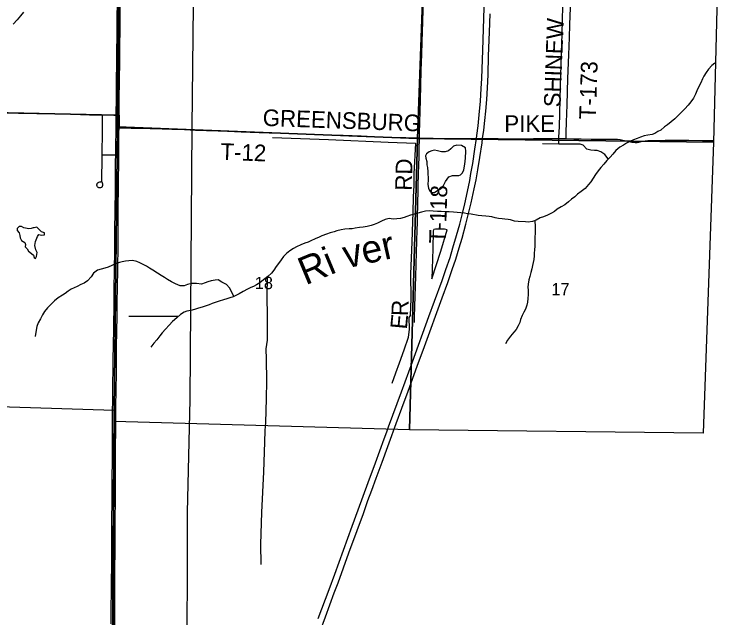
# Model space of a CAD drawing. Extents: x -107 to 120, y -81 to 213.
# Drawn here: x -76.39 to -63.66, y -41 to -30.12 of the extents above; entities that cross this region are included whole.
import ezdxf

# ---------------------------------------------------------------- set-up
doc = ezdxf.new("R2010")
doc.units = 0
for name, color, linetype in [('GM_X_Interstate_Route', 7, 'Continuous'), ('GM_X_Major_River', 7, 'Continuous'), ('GM_X_Minor_Lake', 7, 'Continuous'), ('GM_X_Minor_River', 7, 'Continuous'), ('GM_X_Minor_River_Text', 7, 'Continuous'), ('GM_X_Rail_Line', 7, 'Continuous'), ('GM_X_Section', 7, 'Continuous'), ('GM_X_Section_Text', 7, 'Continuous'), ('GM_X_State_Route', 7, 'Continuous'), ('GM_X_Township', 7, 'Continuous'), ('GM_X_Township_Road', 7, 'Continuous'), ('GM_X_Township_Road_Text', 7, 'Continuous')]:
    doc.layers.add(name, color=color, linetype=linetype)

msp = doc.modelspace()

# ---------------------------------------------------------------- linework, layer by layer
at = {"layer": 'GM_X_Interstate_Route'}
for points in [[(-70.911, -41.015), (-70.716, -40.491), (-70.616, -40.214), (-70.459, -39.782), (-70.302, -39.35), (-70.194, -39.057), (-70.014, -38.564), (-69.883, -38.21), (-69.726, -37.778), (-69.697, -37.701), (-69.67, -37.63), (-69.645, -37.563), (-69.414, -36.931), (-69.217, -36.391), (-68.919, -35.574), (-68.817, -35.297), (-68.682, -34.926), (-68.612, -34.725), (-68.539, -34.507), (-68.486, -34.334), (-68.421, -34.114), (-68.364, -33.908), (-68.315, -33.717), (-68.273, -33.541), (-68.224, -33.317), (-68.184, -33.124), (-68.161, -32.995), (-68.13, -32.817), (-68.09, -32.557), (-68.062, -32.365), (-68.055, -32.313), (-68.033, -32.134), (-68.012, -31.938), (-67.991, -31.693), (-67.976, -31.463), (-67.967, -31.283), (-67.95, -30.774), (-67.93, -30.2), (-67.911, -29.61)], [(-70.883, -41.264), (-70.782, -40.985), (-70.623, -40.554), (-70.556, -40.369), (-70.359, -39.829), (-70.213, -39.428), (-70.1, -39.12), (-70.017, -38.888), (-69.949, -38.703), (-69.868, -38.488), (-69.762, -38.196), (-69.66, -37.918), (-69.587, -37.717), (-69.557, -37.633), (-69.509, -37.501), (-69.407, -37.224), (-69.293, -36.916), (-69.131, -36.468), (-69.001, -36.114), (-68.68, -35.235), (-68.579, -34.958), (-68.498, -34.725), (-68.436, -34.539), (-68.372, -34.335), (-68.322, -34.162), (-68.252, -33.909), (-68.204, -33.718), (-68.158, -33.526), (-68.102, -33.27), (-68.07, -33.109), (-68.038, -32.931), (-68.001, -32.705), (-67.962, -32.445), (-67.952, -32.365), (-67.932, -32.217), (-67.911, -32.038), (-67.895, -31.875), (-67.878, -31.662), (-67.864, -31.449), (-67.854, -31.22), (-67.843, -30.876), (-67.828, -30.449), (-67.817, -30.121)]]:
    msp.add_lwpolyline(points, dxfattribs=at)
at = {"layer": 'GM_X_Major_River'}
for points in [[(-76.22, -30.089), (-76.275, -30.153), (-76.335, -30.225), (-76.405, -30.307)], [(-63.769, -31.007), (-63.824, -31.05), (-63.882, -31.114), (-63.927, -31.175), (-63.97, -31.24), (-63.993, -31.292), (-64.021, -31.362), (-64.066, -31.441), (-64.095, -31.503), (-64.115, -31.567), (-64.154, -31.638), (-64.199, -31.703), (-64.251, -31.765), (-64.31, -31.832), (-64.374, -31.899), (-64.441, -31.962), (-64.492, -32.009), (-64.557, -32.062), (-64.622, -32.119), (-64.673, -32.154), (-64.742, -32.213), (-64.793, -32.238), (-64.85, -32.273), (-64.9, -32.292), (-64.977, -32.307), (-65.041, -32.318), (-65.108, -32.341), (-65.169, -32.366), (-65.235, -32.389), (-65.302, -32.42), (-65.359, -32.451), (-65.412, -32.482), (-65.479, -32.523), (-65.554, -32.579), (-65.605, -32.645), (-65.654, -32.7), (-65.714, -32.759), (-65.767, -32.826), (-65.822, -32.887), (-65.871, -32.947), (-65.917, -33.012), (-65.962, -33.079), (-66.005, -33.143), (-66.043, -33.194), (-66.104, -33.263), (-66.179, -33.322), (-66.24, -33.365), (-66.293, -33.418), (-66.348, -33.459), (-66.405, -33.505), (-66.471, -33.562), (-66.537, -33.596), (-66.606, -33.639), (-66.659, -33.678), (-66.71, -33.71), (-66.785, -33.748), (-66.856, -33.775), (-66.918, -33.792), (-66.989, -33.839), (-67.054, -33.858), (-67.13, -33.871), (-67.18, -33.864), (-67.311, -33.861), (-67.379, -33.852), (-67.447, -33.833)], [(-67.55, -33.817), (-67.602, -33.812), (-67.668, -33.804), (-67.728, -33.792), (-67.786, -33.778), (-67.836, -33.77), (-67.894, -33.765), (-67.968, -33.761), (-68.031, -33.751), (-68.159, -33.731), (-68.221, -33.72), (-68.277, -33.712), (-68.343, -33.702), (-68.409, -33.7), (-68.479, -33.695), (-68.555, -33.687), (-68.615, -33.687), (-68.697, -33.683), (-68.766, -33.679), (-68.842, -33.672), (-68.904, -33.67), (-68.978, -33.674), (-69.05, -33.692), (-69.118, -33.708), (-69.186, -33.73), (-69.253, -33.749), (-69.317, -33.769), (-69.367, -33.787), (-69.431, -33.805), (-69.499, -33.815), (-69.565, -33.817), (-69.637, -33.808), (-69.706, -33.824), (-69.772, -33.854), (-69.842, -33.888), (-69.908, -33.914), (-69.958, -33.93), (-70.032, -33.952), (-70.101, -33.965), (-70.169, -33.971), (-70.245, -33.979), (-70.303, -33.993), (-70.355, -33.995), (-70.431, -34.001), (-70.497, -34.01), (-70.578, -34.026), (-70.628, -34.044), (-70.698, -34.066), (-70.766, -34.088), (-70.846, -34.116), (-70.897, -34.14), (-70.967, -34.171), (-71.045, -34.207), (-71.095, -34.233), (-71.155, -34.253), (-71.226, -34.279), (-71.304, -34.319), (-71.356, -34.349), (-71.422, -34.389), (-71.482, -34.435), (-71.541, -34.491), (-71.583, -34.553), (-71.631, -34.617), (-71.672, -34.673), (-71.712, -34.739), (-71.754, -34.793), (-71.82, -34.851), (-71.899, -34.913), (-71.967, -34.965), (-72.023, -35.001), (-72.077, -35.029), (-72.129, -35.052), (-72.186, -35.078), (-72.264, -35.122), (-72.336, -35.164), (-72.386, -35.188), (-72.445, -35.216), (-72.505, -35.238), (-72.561, -35.254), (-72.621, -35.272), (-72.695, -35.294), (-72.767, -35.321), (-72.82, -35.341), (-72.878, -35.363), (-72.948, -35.387), (-73.002, -35.405), (-73.072, -35.425), (-73.142, -35.447), (-73.207, -35.462), (-73.277, -35.478), (-73.327, -35.494), (-73.393, -35.536), (-73.457, -35.594), (-73.536, -35.664), (-73.6, -35.726), (-73.664, -35.798), (-73.723, -35.868), (-73.763, -35.92), (-73.817, -35.992), (-73.871, -36.054), (-73.928, -36.128)], [(-67.447, -33.833), (-67.49, -33.825), (-67.55, -33.817)]]:
    msp.add_lwpolyline(points, dxfattribs=at)
at = {"layer": 'GM_X_Minor_Lake'}
for p, q in [((-68.957, -32.81), (-68.955, -32.842)), ((-76.028, -33.972), (-76.048, -33.972)), ((-68.64, -34), (-68.801, -33.999))]:
    msp.add_line(p, q, dxfattribs=at)
for points in [[(-68.955, -32.842), (-68.945, -32.89), (-68.936, -32.966), (-68.932, -33.111), (-68.936, -33.195), (-68.926, -33.257), (-68.901, -33.311), (-68.879, -33.335), (-68.821, -33.34), (-68.778, -33.31), (-68.704, -33.272), (-68.66, -33.226), (-68.622, -33.138), (-68.563, -33.056), (-68.493, -33.032), (-68.379, -33.032), (-68.349, -33.022), (-68.313, -32.984), (-68.29, -32.93), (-68.27, -32.826), (-68.262, -32.718), (-68.255, -32.595), (-68.259, -32.533), (-68.333, -32.491), (-68.419, -32.484), (-68.475, -32.502), (-68.527, -32.55), (-68.568, -32.584), (-68.624, -32.604), (-68.692, -32.606), (-68.762, -32.586), (-68.818, -32.576), (-68.868, -32.589), (-68.916, -32.607), (-68.964, -32.641), (-68.981, -32.675), (-68.975, -32.721), (-68.957, -32.78), (-68.957, -32.81)], [(-76.048, -33.972), (-76.083, -33.984), (-76.127, -33.99), (-76.215, -33.974), (-76.259, -33.953), (-76.301, -33.953), (-76.337, -33.989), (-76.337, -34.025), (-76.299, -34.064), (-76.287, -34.11), (-76.283, -34.154), (-76.258, -34.204), (-76.198, -34.238), (-76.186, -34.275), (-76.19, -34.319), (-76.154, -34.351), (-76.13, -34.393), (-76.078, -34.439), (-76.042, -34.468), (-76.028, -34.508), (-76.004, -34.53), (-75.986, -34.492), (-75.972, -34.422), (-75.998, -34.373), (-76.019, -34.291), (-76.003, -34.223), (-75.969, -34.129), (-75.943, -34.095), (-75.895, -34.105), (-75.845, -34.103), (-75.844, -34.067), (-75.894, -34.045), (-75.942, -33.997), (-75.978, -33.96), (-76.028, -33.972)], [(-68.801, -33.999), (-68.831, -34.003), (-68.845, -34.031), (-68.846, -34.352), (-68.864, -34.892), (-68.702, -34.395), (-68.588, -34.01), (-68.64, -34)]]:
    msp.add_lwpolyline(points, dxfattribs=at)
at = {"layer": 'GM_X_Minor_River'}
for points in [[(-66.576, -32.466), (-66.576, -32.339), (-66.566, -32.153), (-66.548, -31.416), (-66.519, -30.474), (-66.499, -29.734), (-66.465, -28.792), (-66.444, -28.009)], [(-71.736, -32.348), (-70.729, -32.383), (-69.655, -32.429), (-69.158, -32.446), (-69.19, -33), (-69.189, -33.21), (-69.201, -33.415), (-69.21, -33.699), (-69.215, -33.858), (-69.224, -34.235), (-69.248, -34.804), (-69.245, -35.253), (-69.254, -35.552), (-69.278, -35.59), (-69.273, -35.799), (-69.292, -35.951), (-69.372, -36.178), (-69.453, -36.412), (-69.52, -36.594), (-69.589, -36.781)], [(-66.233, -32.466), (-66.576, -32.466), (-66.873, -32.46)], [(-65.689, -32.734), (-65.753, -32.651), (-65.825, -32.606), (-65.886, -32.58), (-65.938, -32.58), (-66.003, -32.574), (-66.076, -32.557), (-66.143, -32.486), (-66.193, -32.469), (-66.233, -32.466)], [(-67.009, -33.845), (-67.007, -33.956), (-67.003, -34.028), (-67.008, -34.08), (-67.013, -34.13), (-67.014, -34.196), (-67.011, -34.252), (-67.01, -34.304), (-67.017, -34.368), (-67.022, -34.43), (-67.025, -34.481), (-67.031, -34.547), (-67.044, -34.598), (-67.055, -34.654), (-67.064, -34.716), (-67.081, -34.782), (-67.102, -34.854), (-67.12, -34.914), (-67.133, -34.992), (-67.136, -35.046), (-67.133, -35.1), (-67.133, -35.178), (-67.136, -35.25), (-67.141, -35.317), (-67.156, -35.368), (-67.178, -35.44), (-67.209, -35.492), (-67.242, -35.555), (-67.267, -35.625), (-67.282, -35.681), (-67.314, -35.743), (-67.345, -35.804), (-67.392, -35.857), (-67.45, -35.929), (-67.501, -35.998), (-67.542, -36.065)], [(-72.432, -35.21), (-72.476, -35.122), (-72.512, -35.057), (-72.566, -34.995), (-72.646, -34.951), (-72.716, -34.914), (-72.766, -34.916), (-72.842, -34.932), (-72.898, -34.948), (-72.951, -34.966), (-73.017, -34.992), (-73.103, -34.977), (-73.187, -34.979), (-73.265, -34.997), (-73.329, -35.017), (-73.397, -35.021), (-73.483, -34.986), (-73.555, -34.948), (-73.625, -34.908), (-73.679, -34.872), (-73.743, -34.835), (-73.807, -34.793), (-73.891, -34.739), (-73.949, -34.704), (-74.007, -34.668), (-74.067, -34.636), (-74.125, -34.605), (-74.181, -34.581), (-74.257, -34.563), (-74.324, -34.567), (-74.382, -34.575), (-74.442, -34.587), (-74.494, -34.602), (-74.564, -34.626), (-74.63, -34.656), (-74.694, -34.684), (-74.755, -34.7), (-74.821, -34.722), (-74.891, -34.74), (-74.959, -34.794), (-75.004, -34.858), (-75.066, -34.928), (-75.13, -34.97), (-75.186, -34.995), (-75.257, -35.033), (-75.311, -35.055), (-75.363, -35.079), (-75.415, -35.115), (-75.469, -35.157), (-75.521, -35.185), (-75.596, -35.237), (-75.66, -35.289), (-75.724, -35.351), (-75.789, -35.415), (-75.845, -35.481), (-75.881, -35.543), (-75.915, -35.615), (-75.956, -35.685), (-75.98, -35.751), (-75.99, -35.817), (-76.008, -35.932)], [(-71.83, -34.859), (-71.837, -35.202), (-71.835, -35.581), (-71.832, -35.998), (-71.856, -36.156), (-71.853, -36.339), (-71.844, -36.73), (-71.849, -37.059), (-71.863, -37.484), (-71.877, -37.624), (-71.88, -37.839), (-71.901, -38.37), (-71.936, -39.107), (-71.951, -39.674), (-71.947, -40.043)], [(-73.435, -35.574), (-74.321, -35.572)]]:
    msp.add_lwpolyline(points, dxfattribs=at)
at = {"layer": 'GM_X_Rail_Line'}
for points in [[(-73.273, -42.3), (-73.265, -39.105), (-73.222, -37.066), (-73.184, -32.163), (-73.122, -26.669), (-73.108, -24.298), (-73.059, -17.291), (-73.025, -15.42), (-73.001, -14.708), (-72.977, -14.403), (-72.906, -13.792), (-72.699, -11.694), (-72.659, -11.272), (-72.618, -10.84), (-72.607, -10.553), (-72.601, -10.268), (-72.587, -9.134), (-72.572, -7.013)], [(-74.723, -53.134), (-74.636, -47.862), (-74.58, -37.239), (-74.495, -29.485), (-74.448, -26.625), (-74.401, -23.717), (-74.311, -18.222), (-74.335, -14.312), (-74.219, -9.015)]]:
    msp.add_lwpolyline(points, dxfattribs=at)
at = {"layer": 'GM_X_Section'}
for points in [[(-79.814, -26.495), (-74.457, -26.613), (-74.459, -26.879), (-74.531, -31.942), (-79.874, -31.832)], [(-74.459, -26.879), (-68.933, -27.074), (-69.123, -32.363), (-74.528, -32.154), (-74.531, -31.942)], [(-68.933, -27.074), (-63.66, -27.145), (-63.796, -32.429), (-69.123, -32.363)], [(-79.874, -31.832), (-74.531, -31.942), (-74.528, -32.154), (-74.587, -37.265), (-79.873, -37.1)], [(-74.528, -32.154), (-69.123, -32.363), (-69.266, -37.615), (-74.586, -37.462), (-74.587, -37.265)], [(-69.123, -32.363), (-63.796, -32.429), (-63.978, -37.673), (-69.266, -37.615)]]:
    msp.add_lwpolyline(points, close=True, dxfattribs=at)
at = {"layer": 'GM_X_State_Route'}
for points in [[(-74.484, -30.702), (-74.481, -30.399), (-74.477, -30.087), (-74.474, -29.874), (-74.471, -29.552)], [(-74.641, -41.108), (-74.64, -40.73), (-74.639, -40.627), (-74.639, -40.592), (-74.638, -40.55), (-74.633, -39.861), (-74.631, -39.467), (-74.626, -38.679), (-74.621, -37.973), (-74.619, -37.694), (-74.617, -37.448), (-74.616, -37.268), (-74.616, -37.261), (-74.613, -37.104), (-74.61, -36.825), (-74.605, -36.48), (-74.604, -36.299), (-74.601, -36.136), (-74.59, -35.364), (-74.589, -35.151), (-74.589, -35.102), (-74.58, -34.708), (-74.579, -34.412), (-74.574, -34.035), (-74.57, -33.658), (-74.567, -33.297), (-74.562, -32.886), (-74.562, -32.788), (-74.56, -32.66), (-74.559, -32.624), (-74.56, -32.542), (-74.555, -32.173), (-74.553, -32.017), (-74.553, -31.945), (-74.549, -31.623), (-74.546, -31.295), (-74.543, -31.032), (-74.536, -30.277), (-74.526, -29.832)], [(-74.497, -31.945), (-74.496, -31.843), (-74.495, -31.663), (-74.487, -30.974), (-74.484, -30.702)], [(-74.5, -32.174), (-74.499, -32.04), (-74.497, -31.945)], [(-74.586, -41.691), (-74.579, -40.986), (-74.577, -40.627), (-74.576, -40.592), (-74.576, -40.493), (-74.575, -40.231), (-74.575, -40.066), (-74.572, -39.853), (-74.569, -39.328), (-74.566, -38.786), (-74.563, -38.015), (-74.561, -37.539), (-74.558, -37.262), (-74.558, -37.21), (-74.553, -36.882), (-74.549, -36.603), (-74.545, -36.16), (-74.54, -35.799), (-74.537, -35.602), (-74.535, -35.454), (-74.533, -35.257), (-74.529, -35.11), (-74.527, -34.962), (-74.524, -34.814), (-74.518, -34.191), (-74.516, -33.862), (-74.513, -33.6), (-74.51, -33.255), (-74.504, -32.661), (-74.503, -32.533), (-74.501, -32.27), (-74.5, -32.174)]]:
    msp.add_lwpolyline(points, dxfattribs=at)
at = {"layer": 'GM_X_Township'}
for points in [[(-74.49, -29.164), (-74.527, -31.942), (-74.528, -32.171), (-74.533, -32.658), (-74.589, -37.258), (-74.61, -40.589), (-74.611, -40.624), (-74.622, -42.57)], [(-74.622, -42.57), (-74.611, -40.624), (-74.61, -40.589), (-74.589, -37.258), (-74.533, -32.658), (-74.528, -32.171), (-74.527, -31.942), (-74.49, -29.164)]]:
    msp.add_lwpolyline(points, dxfattribs=at)
at = {"layer": 'GM_X_Township_Road'}
for p, q in [((-74.526, -31.945), (-74.497, -31.945)), ((-74.555, -32.173), (-74.526, -32.173)), ((-74.526, -32.173), (-74.5, -32.174)), ((-74.532, -32.66), (-74.504, -32.661))]:
    msp.add_line(p, q, dxfattribs=at)
for points in [[(-66.448, -32.366), (-66.449, -32.357), (-66.449, -32.319), (-66.448, -32.255), (-66.443, -32.071), (-66.43, -31.76), (-66.414, -31.285), (-66.397, -30.859), (-66.387, -30.547), (-66.378, -30.318), (-66.373, -30.154), (-66.359, -29.744), (-66.341, -29.17), (-66.318, -28.383), (-66.307, -28.023), (-66.301, -27.744), (-66.293, -27.383), (-66.287, -27.203), (-66.282, -27.121)], [(-69.088, -32.355), (-69.086, -32.266), (-69.07, -31.676), (-69.056, -31.137), (-69.047, -30.849), (-69.041, -30.625), (-69.035, -30.445), (-69.03, -30.264), (-69.025, -30.041), (-69.022, -29.936), (-69.02, -29.88), (-69.015, -29.726)], [(-76.805, -31.9), (-76.313, -31.91), (-75.657, -31.921), (-75.361, -31.928), (-75.197, -31.932), (-75.033, -31.936), (-74.82, -31.94), (-74.798, -31.941)], [(-74.804, -32.659), (-74.803, -32.608), (-74.802, -32.499), (-74.801, -32.386), (-74.801, -32.328), (-74.8, -32.247), (-74.8, -32.23), (-74.799, -32.129), (-74.799, -32.049), (-74.798, -31.983), (-74.798, -31.941)], [(-74.798, -31.941), (-74.593, -31.945), (-74.553, -31.945)], [(-74.553, -31.945), (-74.531, -31.945), (-74.526, -31.945)], [(-74.497, -31.945), (-74.499, -32.04), (-74.5, -32.174)], [(-74.5, -32.174), (-74.428, -32.175), (-74.281, -32.178), (-74.134, -32.179), (-73.938, -32.184), (-73.726, -32.191), (-73.547, -32.196), (-73.319, -32.203), (-73.221, -32.209), (-73.126, -32.213)], [(-73.126, -32.213), (-73.122, -32.213), (-73.073, -32.215), (-72.926, -32.222), (-72.712, -32.229), (-72.548, -32.233), (-72.302, -32.243), (-72.138, -32.248), (-71.974, -32.255), (-71.794, -32.261), (-71.318, -32.277), (-70.711, -32.296), (-70.465, -32.305), (-70.137, -32.318), (-69.809, -32.332), (-69.612, -32.338), (-69.333, -32.347), (-69.088, -32.355)], [(-69.179, -35.679), (-69.176, -35.59), (-69.171, -35.389), (-69.155, -34.854), (-69.143, -34.418), (-69.132, -34.011), (-69.127, -33.886), (-69.122, -33.719), (-69.12, -33.614), (-69.117, -33.512), (-69.116, -33.476), (-69.113, -33.364), (-69.11, -33.217), (-69.105, -32.993), (-69.096, -32.695), (-69.092, -32.521), (-69.089, -32.399), (-69.088, -32.355)], [(-69.088, -32.355), (-68.886, -32.361), (-68.844, -32.361)], [(-68.844, -32.361), (-68.705, -32.362), (-68.295, -32.363), (-68.115, -32.364), (-68.062, -32.365), (-67.952, -32.365), (-67.672, -32.367), (-67.344, -32.369), (-67.23, -32.368)], [(-67.23, -32.368), (-67.147, -32.368), (-67.035, -32.366)], [(-67.035, -32.366), (-66.95, -32.364), (-66.851, -32.364), (-66.72, -32.365), (-66.605, -32.366), (-66.448, -32.366)], [(-66.448, -32.366), (-66.442, -32.366), (-66.311, -32.371), (-66.179, -32.373), (-65.999, -32.374), (-65.851, -32.375), (-65.72, -32.376), (-65.654, -32.375), (-65.572, -32.374), (-65.523, -32.377), (-65.475, -32.383), (-65.426, -32.393), (-65.314, -32.419), (-65.266, -32.429), (-65.234, -32.433), (-65.201, -32.435), (-65.168, -32.434), (-65.136, -32.43), (-65.072, -32.415), (-65.023, -32.407), (-64.974, -32.401), (-64.909, -32.398), (-64.662, -32.394), (-64.466, -32.392), (-64.236, -32.397), (-63.99, -32.398), (-63.783, -32.4)], [(-74.81, -33.049), (-74.81, -32.97), (-74.807, -32.855), (-74.806, -32.802), (-74.805, -32.756), (-74.804, -32.69), (-74.804, -32.659)], [(-74.804, -32.659), (-74.768, -32.659), (-74.616, -32.66), (-74.565, -32.66), (-74.56, -32.66)], [(-74.56, -32.66), (-74.548, -32.66), (-74.532, -32.66)], [(-74.82, -33.139), (-74.813, -33.147), (-74.809, -33.153), (-74.806, -33.159), (-74.802, -33.169), (-74.8, -33.178), (-74.798, -33.186), (-74.798, -33.195), (-74.798, -33.207), (-74.8, -33.218), (-74.802, -33.226), (-74.806, -33.233), (-74.811, -33.239), (-74.817, -33.245), (-74.824, -33.249), (-74.832, -33.252), (-74.84, -33.254), (-74.848, -33.255), (-74.858, -33.254), (-74.865, -33.253), (-74.872, -33.249), (-74.879, -33.245), (-74.885, -33.239), (-74.89, -33.233), (-74.894, -33.226), (-74.896, -33.218), (-74.898, -33.21), (-74.899, -33.202), (-74.898, -33.193), (-74.896, -33.185), (-74.893, -33.178), (-74.889, -33.171), (-74.883, -33.165), (-74.877, -33.16), (-74.869, -33.156), (-74.862, -33.153), (-74.846, -33.148), (-74.83, -33.143), (-74.825, -33.14), (-74.822, -33.137), (-74.817, -33.133), (-74.813, -33.126), (-74.811, -33.118), (-74.811, -33.102), (-74.81, -33.049)]]:
    msp.add_lwpolyline(points, dxfattribs=at)

# ---------------------------------------------------------------- texts
at = {"layer": 'GM_X_Minor_River_Text'}
for s, rotation, p in [('ver', 12.5793, (-70.409, -34.709)), ('Ri', 22.5779, (-71.142, -35.013))]:
    msp.add_text(s, height=0.5003, rotation=rotation, dxfattribs=at).set_placement(p)
at = {"layer": 'GM_X_Section_Text'}
for s, p in [('18', (-72.056, -35.079)), ('17', (-66.714, -35.191))]:
    msp.add_text(s, height=0.221, rotation=0, dxfattribs=at).set_placement(p)
at = {"layer": 'GM_X_Township_Road_Text'}
for s, rotation, p in [('SHINEW', 87.8918, (-66.549, -31.806)), ('T-173', 88.0503, (-65.914, -32.023)), ('GREENSBURG', 357.9544, (-71.917, -32.136)), ('PIKE', 0, (-67.561, -32.246)), ('T-12', 357.8816, (-72.678, -32.748)), ('RD', 88.5399, (-69.228, -33.308)), ('T-118', 88.3161, (-68.616, -34.258)), ('R', 87.8349, (-69.295, -35.569)), ('E', 84.6583, (-69.317, -35.811))]:
    msp.add_text(s, height=0.3, rotation=rotation, dxfattribs=at).set_placement(p)

doc.saveas('drawing.dxf')
